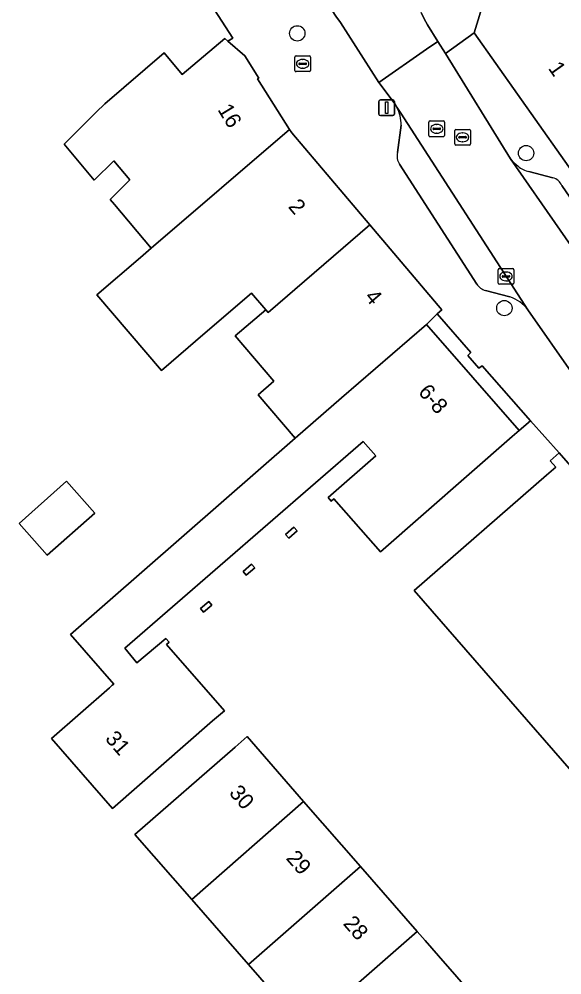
# Model space of a CAD drawing. Extents: x 160663 to 161506, y 382245 to 383291.
# Drawn here: x 160785.3 to 160819.9, y 383094.3 to 383155.3 of the extents above; entities that cross this region are included whole.
import ezdxf

# ---------------------------------------------------------------- set-up
doc = ezdxf.new("R2010")
doc.units = 0
for name, color, linetype in [('IMGEO_Boom', 7, 'Continuous'), ('IMGEO_Erf', 7, 'Continuous'), ('IMGEO_Kolk', 7, 'Continuous'), ('IMGEO_Lichtmast', 7, 'Continuous'), ('IMGEO_Pand', 7, 'Continuous'), ('IMGEO_Pand_nummerreeks', 7, 'Continuous'), ('IMGEO_Parkeervlak_open', 7, 'Continuous'), ('IMGEO_Rijbaan_lokaal_open', 7, 'Continuous'), ('IMGEO_Rioolput', 7, 'Continuous'), ('IMGEO_Voetpad_open', 7, 'Continuous')]:
    doc.layers.add(name, color=color, linetype=linetype)

msp = doc.modelspace()

# ---------------------------------------------------------------- linework, layer by layer
at = {"layer": 'IMGEO_Boom'}
for centre in [(160803.066, 383154.351), (160817.655, 383146.715), (160816.269, 383136.834)]:
    msp.add_circle(centre, 0.489, dxfattribs=at)
at = {"layer": 'IMGEO_Erf'}
msp.add_lwpolyline([(160822.694, 383104.864), (160810.516, 383118.826), (160818.954, 383126.185), (160819.545, 383126.7), (160819.19, 383127.107), (160819.762, 383127.606), (160817.935, 383129.644), (160817.209, 383129.028), (160816.774, 383128.648), (160808.364, 383121.298), (160805.396, 383124.683), (160805.23, 383124.538), (160805.028, 383124.763), (160808.066, 383127.428), (160807.275, 383128.33), (160792.07, 383115.158), (160792.836, 383114.235), (160794.693, 383115.775), (160794.897, 383115.536), (160794.73, 383115.393), (160798.419, 383111.175), (160797.668, 383110.517), (160791.287, 383104.931), (160787.383, 383109.4), (160791.082, 383112.632), (160791.266, 383112.792), (160791.359, 383112.874), (160788.609, 383116.021), (160802.936, 383128.552), (160800.561, 383131.318), (160801.572, 383132.186), (160799.105, 383135.06), (160801.057, 383136.736), (160800.147, 383137.795), (160797.193, 383135.259), (160794.405, 383132.865), (160790.274, 383137.676), (160793.062, 383140.07), (160793.743, 383140.652), (160791.406, 383143.44), (160791.134, 383143.764), (160792.392, 383145.015), (160791.371, 383146.233), (160790.113, 383144.983), (160788.19, 383147.277), (160790.248, 383149.323), (160790.783, 383149.851), (160794.577, 383153.108), (160795.729, 383151.737), (160798.448, 383154.014), (160798.64, 383153.847), (160798.946, 383154.044), (160793.732, 383162.132)], dxfattribs=at)
for points in [[(160790.164, 383123.757), (160787.116, 383121.091), (160785.327, 383123.112), (160788.359, 383125.797)], [(160802.856, 383122.873), (160803.059, 383122.64), (160802.527, 383122.176), (160802.323, 383122.409)], [(160800.149, 383120.505), (160800.351, 383120.27), (160799.812, 383119.809), (160799.61, 383120.044)], [(160797.417, 383118.141), (160797.62, 383117.906), (160797.089, 383117.445), (160796.885, 383117.679)], [(160811.213, 383096.528), (160812.072, 383095.545), (160814.412, 383092.867), (160804.784, 383084.465), (160802.28, 383087.331), (160804.744, 383089.502), (160803.563, 383090.856), (160799.947, 383095.001), (160796.331, 383099.146), (160792.715, 383103.29), (160799.098, 383108.859), (160799.86, 383109.524), (160803.47, 383105.392), (160807.088, 383101.25), (160810.707, 383097.108)]]:
    msp.add_lwpolyline(points, close=True, dxfattribs=at)
at = {"layer": 'IMGEO_Kolk'}
for p, q in [((160815.875, 383138.429), (160815.875, 383139.281)), ((160815.95, 383139.355), (160816.802, 383139.355)), ((160816.134, 383138.849), (160816.134, 383138.861)), ((160816.572, 383138.812), (160816.174, 383138.812)), ((160816.177, 383138.898), (160816.575, 383138.898)), ((160816.363, 383139.135), (160816.388, 383139.135)), ((160816.618, 383138.861), (160816.618, 383138.849)), ((160816.876, 383139.281), (160816.876, 383138.429)), ((160816.802, 383138.355), (160815.95, 383138.355)), ((160816.386, 383138.575), (160816.361, 383138.575))]:
    msp.add_line(p, q, dxfattribs=at)
for points in [[(160815.875, 383138.429), (160815.875, 383139.281)], [(160815.95, 383139.355), (160816.802, 383139.355)], [(160816.876, 383139.281), (160816.876, 383138.429)], [(160816.802, 383138.355), (160815.95, 383138.355)]]:
    msp.add_lwpolyline(points, dxfattribs=at)
for centre, radius, start, end in [((160815.952, 383139.279), 0.0765, 91.55205, 178.44795), ((160815.952, 383139.279), 0.0765, 91.55205, 178.44795), ((160816.174, 383138.858), 0.0403, 85.87752, 175.75265), ((160816.171, 383138.848), 0.0366, 178.93798, 274.71019), ((160816.575, 383138.855), 0.043, 264.86636, 352.45326), ((160816.579, 383138.86), 0.0386, 1.73085, 96.63898), ((160816.8, 383139.279), 0.0765, 1.55205, 88.44795), ((160816.8, 383139.279), 0.0765, 1.55205, 88.44795), ((160815.952, 383138.431), 0.0765, 181.55205, 268.44795), ((160815.952, 383138.431), 0.0765, 181.55205, 268.44795), ((160816.8, 383138.431), 0.0765, 271.55205, 358.44795), ((160816.8, 383138.431), 0.0765, 271.55205, 358.44795)]:
    msp.add_arc(centre, radius, start, end, dxfattribs=at)
for centre, major_axis, ratio, start_param, end_param in [((160816.362, 383138.855), (-0.387, 0.002), 0.722429, 4.712389, 7.853982), ((160816.387, 383138.855), (-0.39, 0.002), 0.717154, 1.570796, 4.712389)]:
    msp.add_ellipse(centre, major_axis=major_axis, ratio=ratio, start_param=start_param, end_param=end_param, dxfattribs=at)
at = {"layer": 'IMGEO_Lichtmast'}
for p, q in [((160808.267, 383149.207), (160808.267, 383150.007)), ((160808.267, 383150.007), (160808.267, 383149.207)), ((160808.367, 383150.107), (160809.157, 383150.107)), ((160809.157, 383150.107), (160808.367, 383150.107)), ((160809.257, 383150.007), (160809.257, 383149.207)), ((160809.257, 383149.207), (160809.257, 383150.007)), ((160809.157, 383149.107), (160808.367, 383149.107)), ((160808.367, 383149.107), (160809.157, 383149.107))]:
    msp.add_line(p, q, dxfattribs=at)
msp.add_lwpolyline([(160808.687, 383149.982), (160808.837, 383149.982), (160808.837, 383149.232), (160808.687, 383149.232), (160808.687, 383149.982)], dxfattribs=at)
for centre, start, end in [((160808.367, 383150.007), 90, 180), ((160808.367, 383150.007), 90, 180), ((160809.157, 383150.007), 0, 90), ((160809.157, 383150.007), 360, 90), ((160808.367, 383149.207), 180, 270), ((160808.367, 383149.207), 180, 270), ((160809.157, 383149.207), 270, 0), ((160809.157, 383149.207), 270, 0)]:
    msp.add_arc(centre, 0.1, start, end, dxfattribs=at)
at = {"layer": 'IMGEO_Pand'}
for points in [[(160818.613, 383159.104), (160815.008, 383156.554), (160814.35, 383154.373), (160821.254, 383144.609), (160822.38, 383145.405), (160820.912, 383147.471), (160823.084, 383149.009), (160821.915, 383150.662), (160823.694, 383151.92)], [(160800.53, 383151.447), (160800.615, 383151.501), (160799.714, 383152.911), (160798.64, 383153.847), (160798.448, 383154.014), (160795.729, 383151.737), (160794.577, 383153.108), (160790.783, 383149.851), (160790.248, 383149.323), (160788.19, 383147.277), (160790.113, 383144.983), (160791.371, 383146.233), (160792.392, 383145.015), (160791.134, 383143.764), (160791.406, 383143.44), (160793.743, 383140.652), (160802.566, 383148.229)], [(160807.695, 383142.137), (160802.712, 383147.999), (160802.566, 383148.229), (160793.743, 383140.652), (160793.062, 383140.07), (160790.274, 383137.676), (160794.405, 383132.865), (160797.193, 383135.259), (160800.147, 383137.795), (160801.057, 383136.736), (160801.205, 383136.563)], [(160811.296, 383135.788), (160811.985, 383136.471), (160812.29, 383136.731), (160807.695, 383142.137), (160801.205, 383136.563), (160801.057, 383136.736), (160799.105, 383135.06), (160801.572, 383132.186), (160800.561, 383131.318), (160802.936, 383128.552), (160805.876, 383131.123)], [(160816.774, 383128.648), (160817.209, 383129.028), (160811.296, 383135.788), (160805.876, 383131.123), (160802.936, 383128.552), (160788.609, 383116.021), (160791.359, 383112.874), (160791.266, 383112.792), (160791.082, 383112.632), (160787.383, 383109.4), (160791.287, 383104.931), (160797.668, 383110.517), (160798.419, 383111.175), (160794.73, 383115.393), (160794.897, 383115.536), (160794.693, 383115.775), (160792.836, 383114.235), (160792.07, 383115.158), (160807.275, 383128.33), (160808.066, 383127.428), (160805.028, 383124.763), (160805.23, 383124.538), (160805.396, 383124.683), (160808.364, 383121.298)], [(160790.164, 383123.757), (160788.359, 383125.797), (160785.327, 383123.112), (160787.116, 383121.091)], [(160803.059, 383122.64), (160802.856, 383122.873), (160802.323, 383122.409), (160802.527, 383122.176)], [(160800.351, 383120.27), (160800.149, 383120.505), (160799.61, 383120.044), (160799.812, 383119.809)], [(160797.62, 383117.906), (160797.417, 383118.141), (160796.885, 383117.679), (160797.089, 383117.445)], [(160803.47, 383105.392), (160799.86, 383109.524), (160799.098, 383108.859), (160792.715, 383103.29), (160796.331, 383099.146)], [(160799.947, 383095.001), (160807.088, 383101.25), (160803.47, 383105.392), (160796.331, 383099.146)], [(160799.947, 383095.001), (160803.563, 383090.856), (160810.707, 383097.108), (160807.088, 383101.25)], [(160810.707, 383097.108), (160803.563, 383090.856), (160804.744, 383089.502), (160802.28, 383087.331), (160804.784, 383084.465), (160814.412, 383092.867), (160812.072, 383095.545), (160811.213, 383096.528)]]:
    msp.add_lwpolyline(points, close=True, dxfattribs=at)
msp.add_lwpolyline([(160809.442, 383063.5), (160847.06, 383096.364), (160841.583, 383102.623), (160834.141, 383111.138), (160833.817, 383110.855), (160834.034, 383110.607), (160833.281, 383109.948), (160833.064, 383110.197), (160832.876, 383110.032), (160831.551, 383111.552), (160831.739, 383111.716), (160831.522, 383111.965), (160832.275, 383112.623), (160832.492, 383112.374), (160832.816, 383112.657), (160819.762, 383127.606), (160819.19, 383127.107), (160819.545, 383126.7), (160818.954, 383126.185), (160810.516, 383118.826), (160822.694, 383104.864), (160825.95, 383107.704), (160832.337, 383100.4), (160801.258, 383073.294)], dxfattribs=at)
at = {"layer": 'IMGEO_Parkeervlak_open'}
for points in [[(160809.67, 383149.259), (160809.419, 383149.635)], [(160817.769, 383136.732), (160809.67, 383149.259)], [(160809.685, 383148.494), (160809.455, 383146.746)], [(160816.664, 383146.344), (160826.168, 383132.701)], [(160809.581, 383146.004), (160814.514, 383138.365)], [(160819.36, 383145.139), (160817.839, 383145.534)], [(160822.795, 383140.456), (160819.939, 383144.65)], [(160815.064, 383137.955), (160816.623, 383137.554)]]:
    msp.add_lwpolyline(points, dxfattribs=at)
for centre, radius, start, end in [((160807.448, 383148.574), 2.238, 357.94905, 28.29677), ((160810.409, 383146.526), 0.979, 167.02828, 212.2468), ((160819.696, 383149.053), 4.066, 221.77239, 231.15272), ((160818.184, 383147.071), 1.575, 228.79064, 257.354), ((160819.151, 383144.305), 0.86, 23.66792, 75.96591), ((160815.337, 383138.896), 0.979, 212.7981, 253.79619), ((160815.786, 383135.178), 2.52, 38.09594, 70.60202)]:
    msp.add_arc(centre, radius, start, end, dxfattribs=at)
at = {"layer": 'IMGEO_Rijbaan_lokaal_open'}
msp.add_lwpolyline([(160799.007, 383165.568), (160805.524, 383155.451), (160805.814, 383155.045), (160808.268, 383151.222), (160811.308, 383153.342), (160812.035, 383153.83), (160811.368, 383154.9), (160811.164, 383155.266), (160810.957, 383155.675)], dxfattribs=at)
msp.add_lwpolyline([(160827.416, 383131.144), (160826.168, 383132.701), (160816.664, 383146.344), (160812.51, 383153.063), (160812.035, 383153.83), (160811.308, 383153.342), (160808.268, 383151.222), (160809.298, 383149.833), (160809.419, 383149.635), (160809.67, 383149.259), (160817.769, 383136.732), (160820.684, 383132.561), (160821.531, 383131.367), (160822.35, 383130.236), (160823.047, 383129.367), (160823.481, 383128.851), (160825.101, 383126.939), (160847.955, 383100.412), (160851.37, 383103.314), (160850.081, 383104.819), (160838.779, 383117.869)], close=True, dxfattribs=at)
at = {"layer": 'IMGEO_Rioolput'}
for p, q in [((160802.909, 383151.982), (160802.909, 383152.834)), ((160802.984, 383152.908), (160803.836, 383152.908)), ((160803.91, 383152.834), (160803.91, 383151.982)), ((160803.168, 383152.402), (160803.168, 383152.414)), ((160803.606, 383152.365), (160803.208, 383152.365)), ((160803.211, 383152.451), (160803.609, 383152.451)), ((160803.397, 383152.688), (160803.422, 383152.688)), ((160803.652, 383152.414), (160803.652, 383152.402)), ((160803.836, 383151.908), (160802.984, 383151.908)), ((160803.42, 383152.128), (160803.395, 383152.128)), ((160811.459, 383147.838), (160811.459, 383148.69)), ((160811.534, 383148.764), (160812.386, 383148.764)), ((160811.947, 383148.544), (160811.972, 383148.544)), ((160812.46, 383148.69), (160812.46, 383147.838)), ((160811.718, 383148.258), (160811.718, 383148.27)), ((160812.156, 383148.221), (160811.758, 383148.221)), ((160811.761, 383148.307), (160812.159, 383148.307)), ((160811.97, 383147.984), (160811.945, 383147.984)), ((160812.202, 383148.27), (160812.202, 383148.258)), ((160813.103, 383147.299), (160813.103, 383148.151)), ((160813.178, 383148.225), (160814.03, 383148.225)), ((160813.591, 383148.005), (160813.616, 383148.005)), ((160814.104, 383148.151), (160814.104, 383147.299)), ((160812.386, 383147.764), (160811.534, 383147.764)), ((160813.362, 383147.719), (160813.362, 383147.731)), ((160813.8, 383147.682), (160813.402, 383147.682)), ((160813.405, 383147.768), (160813.803, 383147.768)), ((160813.614, 383147.445), (160813.589, 383147.445)), ((160813.846, 383147.731), (160813.846, 383147.719)), ((160814.03, 383147.225), (160813.178, 383147.225))]:
    msp.add_line(p, q, dxfattribs=at)
for points in [[(160802.909, 383151.982), (160802.909, 383152.834)], [(160802.984, 383152.908), (160803.836, 383152.908)], [(160803.91, 383152.834), (160803.91, 383151.982)], [(160803.836, 383151.908), (160802.984, 383151.908)], [(160811.459, 383147.838), (160811.459, 383148.69)], [(160811.534, 383148.764), (160812.386, 383148.764)], [(160812.46, 383148.69), (160812.46, 383147.838)], [(160813.103, 383147.299), (160813.103, 383148.151)], [(160813.178, 383148.225), (160814.03, 383148.225)], [(160814.104, 383148.151), (160814.104, 383147.299)], [(160812.386, 383147.764), (160811.534, 383147.764)], [(160814.03, 383147.225), (160813.178, 383147.225)]]:
    msp.add_lwpolyline(points, dxfattribs=at)
for centre, radius, start, end in [((160802.986, 383152.832), 0.0765, 91.55205, 178.44795), ((160802.986, 383152.832), 0.0765, 91.55205, 178.44795), ((160803.834, 383152.832), 0.0765, 1.55205, 88.44795), ((160803.834, 383152.832), 0.0765, 1.55205, 88.44795), ((160803.208, 383152.411), 0.0403, 85.87752, 175.75265), ((160803.205, 383152.401), 0.0366, 178.93798, 274.71019), ((160803.609, 383152.408), 0.043, 264.86636, 352.45326), ((160803.613, 383152.413), 0.0386, 1.73085, 96.63898), ((160802.986, 383151.984), 0.0765, 181.55205, 268.44795), ((160802.986, 383151.984), 0.0765, 181.55205, 268.44795), ((160803.834, 383151.984), 0.0765, 271.55205, 358.44795), ((160803.834, 383151.984), 0.0765, 271.55205, 358.44795), ((160811.536, 383148.688), 0.0765, 91.55205, 178.44795), ((160811.536, 383148.688), 0.0765, 91.55205, 178.44795), ((160812.384, 383148.688), 0.0765, 1.55205, 88.44795), ((160812.384, 383148.688), 0.0765, 1.55205, 88.44795), ((160811.758, 383148.267), 0.0403, 85.87752, 175.75265), ((160811.755, 383148.257), 0.0366, 178.93798, 274.71019), ((160812.159, 383148.264), 0.043, 264.86636, 352.45326), ((160812.163, 383148.269), 0.0386, 1.73085, 96.63898), ((160813.18, 383148.149), 0.0765, 91.55205, 178.44795), ((160813.18, 383148.149), 0.0765, 91.55205, 178.44795), ((160814.028, 383148.149), 0.0765, 1.55205, 88.44795), ((160814.028, 383148.149), 0.0765, 1.55205, 88.44795), ((160811.536, 383147.84), 0.0765, 181.55205, 268.44795), ((160811.536, 383147.84), 0.0765, 181.55205, 268.44795), ((160812.384, 383147.84), 0.0765, 271.55205, 358.44795), ((160812.384, 383147.84), 0.0765, 271.55205, 358.44795), ((160813.18, 383147.301), 0.0765, 181.55205, 268.44795), ((160813.18, 383147.301), 0.0765, 181.55205, 268.44795), ((160813.402, 383147.728), 0.0403, 85.87752, 175.75265), ((160813.399, 383147.718), 0.0366, 178.93798, 274.71019), ((160813.803, 383147.725), 0.043, 264.86636, 352.45326), ((160813.807, 383147.73), 0.0386, 1.73085, 96.63898), ((160814.028, 383147.301), 0.0765, 271.55205, 358.44795), ((160814.028, 383147.301), 0.0765, 271.55205, 358.44795)]:
    msp.add_arc(centre, radius, start, end, dxfattribs=at)
for centre, major_axis, ratio, start_param, end_param in [((160803.396, 383152.408), (-0.387, 0.002), 0.722429, 4.712389, 7.853982), ((160803.421, 383152.408), (-0.39, 0.002), 0.717154, 1.570796, 4.712389), ((160811.946, 383148.264), (-0.387, 0.002), 0.722429, 4.712389, 7.853982), ((160811.971, 383148.264), (-0.39, 0.002), 0.717154, 1.570796, 4.712389), ((160813.59, 383147.725), (-0.387, 0.002), 0.722429, 4.712389, 7.853982), ((160813.615, 383147.725), (-0.39, 0.002), 0.717154, 1.570796, 4.712389)]:
    msp.add_ellipse(centre, major_axis=major_axis, ratio=ratio, start_param=start_param, end_param=end_param, dxfattribs=at)
at = {"layer": 'IMGEO_Voetpad_open'}
for points in [[(160810.957, 383155.675), (160811.164, 383155.266), (160811.368, 383154.9), (160812.035, 383153.83), (160812.51, 383153.063), (160814.35, 383154.373), (160815.008, 383156.554), (160818.613, 383159.104), (160824.34, 383163.154), (160830.982, 383167.851), (160841.512, 383175.298), (160846.479, 383178.81), (160851.374, 383182.272), (160860.186, 383188.504)], [(160809.419, 383149.635), (160809.298, 383149.833), (160808.268, 383151.222), (160805.814, 383155.045), (160805.524, 383155.451), (160799.007, 383165.568)], [(160793.732, 383162.132), (160798.946, 383154.044), (160798.64, 383153.847), (160799.714, 383152.911), (160800.615, 383151.501), (160800.53, 383151.447), (160802.566, 383148.229), (160802.712, 383147.999), (160807.695, 383142.137), (160812.29, 383136.731), (160811.985, 383136.471), (160814.142, 383134.007), (160813.937, 383133.818), (160814.65, 383133.011), (160814.854, 383133.148), (160817.935, 383129.644), (160819.762, 383127.606), (160832.816, 383112.657), (160834.141, 383111.138), (160841.583, 383102.623), (160847.06, 383096.364), (160848.555, 383094.624)], [(160859.34, 383099.047), (160854.573, 383104.237), (160854.382, 383104.456), (160854.457, 383104.522), (160854.374, 383104.619), (160850.691, 383108.893), (160850.763, 383108.963), (160846.774, 383113.543), (160846.678, 383113.478), (160840.66, 383120.426), (160838.066, 383123.41), (160834.654, 383127.38), (160832.992, 383129.701), (160832.886, 383129.618), (160828.567, 383135.162), (160827.356, 383136.717), (160823.035, 383142.262), (160821.254, 383144.609), (160814.35, 383154.373), (160812.51, 383153.063), (160816.664, 383146.344)], [(160809.455, 383146.746), (160809.685, 383148.494)], [(160814.514, 383138.365), (160809.581, 383146.004)], [(160817.839, 383145.534), (160819.36, 383145.139)], [(160819.939, 383144.65), (160822.795, 383140.456), (160825.92, 383135.981)], [(160816.623, 383137.554), (160815.064, 383137.955)], [(160825.101, 383126.939), (160823.481, 383128.851), (160823.047, 383129.367), (160822.35, 383130.236), (160821.531, 383131.367), (160820.684, 383132.561), (160817.769, 383136.732)]]:
    msp.add_lwpolyline(points, dxfattribs=at)
msp.add_lwpolyline([(160817.935, 383129.644), (160814.854, 383133.148), (160814.65, 383133.011), (160813.937, 383133.818), (160814.142, 383134.007), (160811.985, 383136.471), (160811.296, 383135.788), (160817.209, 383129.028)], close=True, dxfattribs=at)
for centre, radius, start, end in [((160807.448, 383148.574), 2.238, 357.94905, 28.29677), ((160810.409, 383146.526), 0.979, 167.02828, 212.2468), ((160819.696, 383149.053), 4.066, 221.77239, 231.15272), ((160818.184, 383147.071), 1.575, 228.79064, 257.354), ((160819.151, 383144.305), 0.86, 23.66792, 75.96591), ((160815.337, 383138.896), 0.979, 212.7981, 253.79619), ((160815.786, 383135.178), 2.52, 38.09594, 70.60202)]:
    msp.add_arc(centre, radius, start, end, dxfattribs=at)

# ---------------------------------------------------------------- texts
at = {"layer": 'IMGEO_Pand_nummerreeks'}
for s, rotation, p in [('1', 305.26364, (160819.029, 383152.121)), ('16', 301.35204, (160797.956, 383149.491)), ('2', 310.08965, (160802.443, 383143.283)), ('4', 310.36467, (160807.315, 383137.52)), ('6-8', 311.17827, (160810.727, 383131.457)), ('31', 311.13816, (160790.764, 383109.36)), ('30', 311.14133, (160798.667, 383105.904)), ('29', 311.14133, (160802.303, 383101.742)), ('28', 311.14133, (160805.943, 383097.575))]:
    msp.add_text(s, height=1, rotation=rotation, dxfattribs=at).set_placement(p)

doc.saveas('drawing.dxf')
